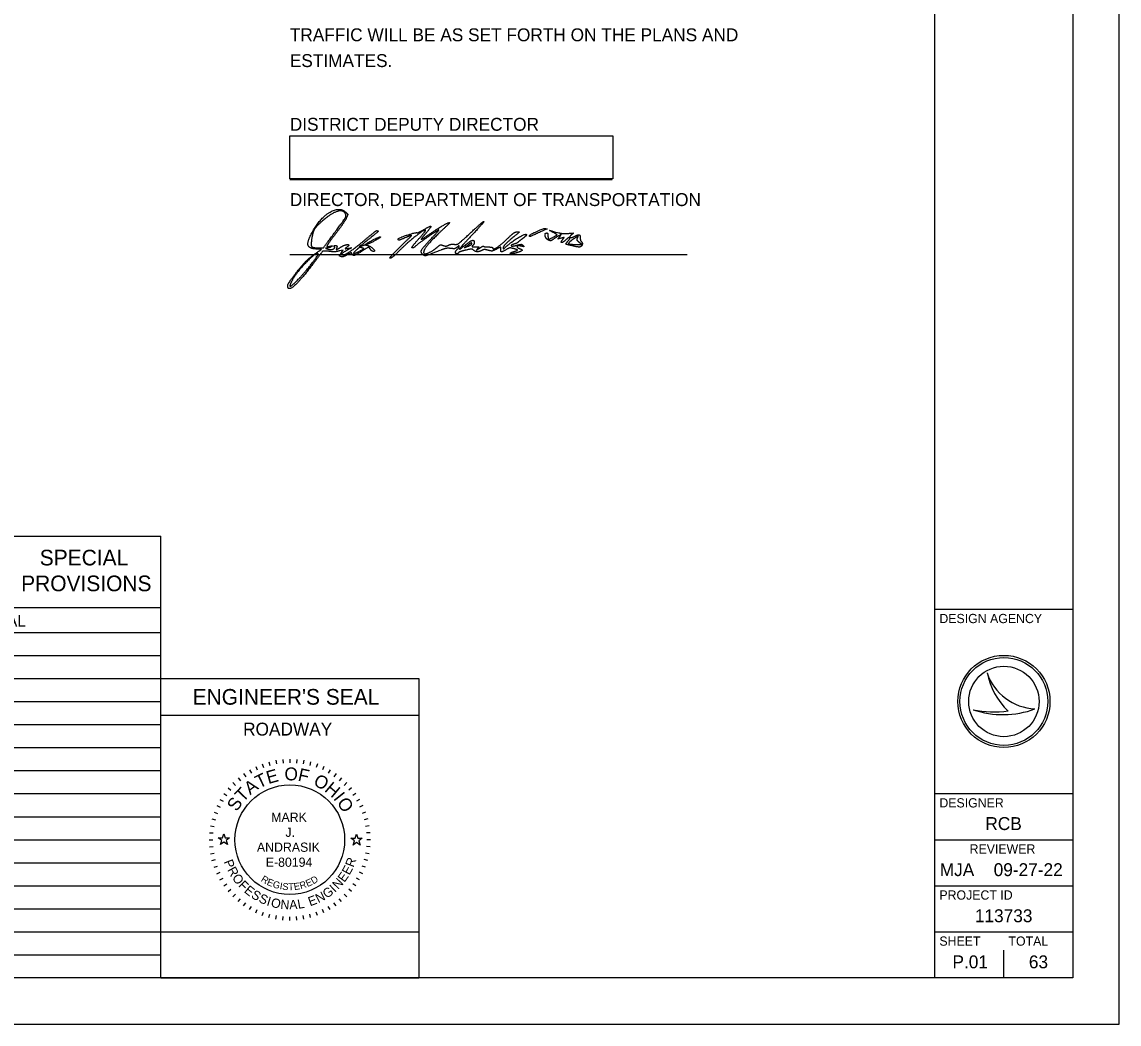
# Model space of a CAD drawing. Extents: x 0 to 34, y 0 to 22.
# Drawn here: x 22.09 to 34, y 0 to 10.87 of the extents above; entities that cross this region are included whole.
import ezdxf

# ---------------------------------------------------------------- set-up
doc = ezdxf.new("R2010")
doc.units = 0
for name, color, linetype in [('SH_Border', 7, 'Continuous'), ('SH_Cut_Line', 7, 'Continuous'), ('SH_Data', 7, 'Continuous'), ('SH_Text', 7, 'Continuous')]:
    doc.layers.add(name, color=color, linetype=linetype)

msp = doc.modelspace()

# ---------------------------------------------------------------- linework, layer by layer
at = {"layer": 'SH_Border'}
for p, q in [((32, 0.5), (32, 21.5)), ((32, 4.5), (33.5, 4.5)), ((32, 2.5), (33.5, 2.5)), ((32, 2), (33.5, 2)), ((32, 1.5), (33.5, 1.5)), ((32, 1), (33.5, 1))]:
    msp.add_line(p, q, dxfattribs=at)
msp.add_lwpolyline([(1.5, 21.5), (33.5, 21.5), (33.5, 0.5), (1.5, 0.5)], close=True, dxfattribs=at)
at = {"layer": 'SH_Cut_Line'}
msp.add_lwpolyline([(0, 0), (34, 0), (34, 22), (0, 22)], close=True, dxfattribs=at)
at = {"layer": 'SH_Data'}
for p, q in [((25, 9.162), (28.5, 9.162)), ((25, 8.348), (29.314, 8.348)), ((10.15, 5.292), (23.6, 5.292)), ((23.6, 0.5), (23.6, 5.292)), ((10.15, 4.521), (23.6, 4.521)), ((10.15, 4.25), (23.6, 4.25)), ((10.15, 4), (23.6, 4)), ((10.15, 3.75), (23.6, 3.75)), ((23.6, 0.5), (23.6, 3.75)), ((23.6, 3.75), (26.4, 3.75)), ((26.4, 3.75), (26.4, 0.5)), ((32.567, 3.81), (32.567, 3.81)), ((10.15, 3.5), (23.6, 3.5)), ((32.75, 3.5), (32.75, 3.5)), ((23.6, 3.35), (26.4, 3.35)), ((32.417, 3.41), (32.417, 3.41)), ((33.087, 3.419), (33.087, 3.419)), ((10.15, 3.25), (23.6, 3.25)), ((10.15, 3), (23.6, 3)), ((24.848, 2.862), (24.855, 2.822)), ((24.924, 2.872), (24.927, 2.832)), ((25, 2.875), (25, 2.835)), ((25.076, 2.872), (25.073, 2.832)), ((25.152, 2.862), (25.145, 2.822)), ((10.15, 2.75), (23.6, 2.75)), ((24.563, 2.758), (24.583, 2.723)), ((24.63, 2.793), (24.647, 2.757)), ((24.701, 2.822), (24.714, 2.785)), ((24.774, 2.845), (24.784, 2.807)), ((25.226, 2.845), (25.216, 2.807)), ((25.299, 2.822), (25.286, 2.785)), ((25.37, 2.793), (25.353, 2.757)), ((25.437, 2.758), (25.417, 2.723)), ((24.438, 2.67), (24.463, 2.64)), ((24.498, 2.717), (24.521, 2.684)), ((25.502, 2.717), (25.479, 2.684)), ((25.562, 2.67), (25.537, 2.64)), ((24.283, 2.502), (24.316, 2.479)), ((24.33, 2.562), (24.36, 2.537)), ((24.381, 2.619), (24.41, 2.59)), ((25.619, 2.619), (25.59, 2.59)), ((25.67, 2.562), (25.64, 2.537)), ((25.717, 2.502), (25.684, 2.479)), ((10.15, 2.5), (23.6, 2.5)), ((24.242, 2.438), (24.277, 2.418)), ((25.758, 2.438), (25.723, 2.418)), ((24.178, 2.299), (24.215, 2.286)), ((24.207, 2.37), (24.243, 2.353)), ((25.793, 2.37), (25.757, 2.353)), ((25.822, 2.299), (25.785, 2.286)), ((10.15, 2.25), (23.6, 2.25)), ((24.138, 2.152), (24.178, 2.145)), ((24.155, 2.226), (24.193, 2.216)), ((25.845, 2.226), (25.807, 2.216)), ((25.862, 2.152), (25.822, 2.145)), ((24.128, 2.076), (24.168, 2.073)), ((25.872, 2.076), (25.832, 2.073)), ((10.15, 2), (23.6, 2)), ((24.125, 2), (24.165, 2)), ((24.128, 1.924), (24.168, 1.927)), ((25.872, 1.924), (25.832, 1.927)), ((25.875, 2), (25.835, 2)), ((24.138, 1.848), (24.178, 1.855)), ((25.862, 1.848), (25.822, 1.855)), ((10.15, 1.75), (23.6, 1.75)), ((24.155, 1.774), (24.193, 1.784)), ((24.178, 1.701), (24.215, 1.714)), ((25.822, 1.701), (25.785, 1.714)), ((25.845, 1.774), (25.807, 1.784)), ((24.207, 1.63), (24.243, 1.647)), ((24.242, 1.563), (24.277, 1.583)), ((25.758, 1.563), (25.723, 1.583)), ((25.793, 1.63), (25.757, 1.647)), ((10.15, 1.5), (23.6, 1.5)), ((24.283, 1.498), (24.316, 1.521)), ((24.33, 1.438), (24.36, 1.463)), ((25.67, 1.438), (25.64, 1.463)), ((25.717, 1.498), (25.684, 1.521)), ((24.381, 1.381), (24.41, 1.41)), ((24.438, 1.33), (24.463, 1.36)), ((24.498, 1.283), (24.521, 1.316)), ((25.502, 1.283), (25.479, 1.316)), ((25.562, 1.33), (25.537, 1.36)), ((25.619, 1.381), (25.59, 1.41)), ((10.15, 1.25), (23.6, 1.25)), ((24.563, 1.242), (24.583, 1.277)), ((24.63, 1.207), (24.647, 1.243)), ((24.701, 1.178), (24.714, 1.215)), ((24.774, 1.155), (24.784, 1.193)), ((25.226, 1.155), (25.216, 1.193)), ((25.299, 1.178), (25.286, 1.215)), ((25.37, 1.207), (25.353, 1.243)), ((25.437, 1.242), (25.417, 1.277)), ((24.848, 1.138), (24.855, 1.178)), ((24.924, 1.128), (24.927, 1.168)), ((25, 1.125), (25, 1.165)), ((25.076, 1.128), (25.073, 1.168)), ((25.152, 1.138), (25.145, 1.178)), ((10.15, 1), (23.6, 1)), ((10.15, 0.75), (23.6, 0.75)), ((32.75, 0.5), (32.75, 0.8)), ((32.375, 0.675), (32.375, 0.675)), ((23.6, 0.5), (26.4, 0.5))]:
    msp.add_line(p, q, dxfattribs=at)
for points in [[(25, 9.172), (25, 9.637), (28.504, 9.637), (28.504, 9.172)], [(24.224, 2.02), (24.271, 2.02), (24.285, 2.065), (24.299, 2.02), (24.346, 2.02), (24.308, 1.992), (24.323, 1.948), (24.285, 1.975), (24.247, 1.948), (24.262, 1.992)], [(25.663, 2.015), (25.71, 2.015), (25.724, 2.059), (25.739, 2.015), (25.785, 2.015), (25.748, 1.987), (25.762, 1.942), (25.724, 1.97), (25.686, 1.942), (25.701, 1.987)], [(23.6, 0.5), (23.6, 1), (26.4, 1), (26.4, 0.5)]]:
    msp.add_lwpolyline(points, close=True, dxfattribs=at)
for centre, radius in [((32.75, 3.5), 0.5), ((32.75, 3.5), 0.477), ((32.75, 3.5), 0.477), ((32.75, 3.5), 0.382), ((25, 2), 0.595)]:
    msp.add_circle(centre, radius, dxfattribs=at)
for centre, radius, start, end in [((33.116, 3.998), 0.58, 198.9257, 198.9319), ((33.347, 3.97), 0.796, 191.6379, 191.6421), ((33.116, 3.998), 0.58, 198.9319, 267.1657), ((33.347, 3.97), 0.796, 191.6421, 226.0947), ((32.739, 4.37), 1.013, 251.4576, 290.0832), ((32.648, 4.654), 1.266, 259.4964, 259.4995), ((32.739, 4.37), 1.013, 251.4527, 251.4576), ((32.648, 4.654), 1.266, 259.4995, 276.6672)]:
    msp.add_arc(centre, radius, start, end, dxfattribs=at)
at = {"layer": 'SH_Text'}
for p, q in [((25.462, 8.553), (25.462, 8.553)), ((25.828, 8.463), (25.828, 8.463)), ((26.977, 8.465), (26.977, 8.465)), ((27.602, 8.552), (27.602, 8.552)), ((25.783, 8.421), (25.783, 8.421)), ((26.199, 8.434), (26.199, 8.434)), ((28.054, 8.446), (28.054, 8.446)), ((24.977, 8.013), (24.977, 8.013)), ((25.092, 8.08), (25.092, 8.08))]:
    msp.add_line(p, q, dxfattribs=at)
for points in [[(27.865, 8.542), (27.902, 8.564), (27.861, 8.587)], [(28.114, 8.459), (28.17, 8.459), (28.142, 8.481)], [(25.315, 8.386), (25.345, 8.407), (25.307, 8.408)], [(25.558, 8.366), (25.579, 8.398), (25.537, 8.388)], [(26.925, 8.445), (26.895, 8.42), (26.936, 8.439)]]:
    msp.add_lwpolyline(points, dxfattribs=at)
for points in [[(25.251, 8.604), (25.337, 8.754), (25.545, 8.87), (25.611, 8.804)], [(25.602, 8.795), (25.576, 8.837), (25.45, 8.796), (25.355, 8.714)], [(25.355, 8.714), (25.288, 8.657), (25.249, 8.593), (25.238, 8.522)], [(25.462, 8.553), (25.584, 8.716), (25.616, 8.772), (25.602, 8.795)], [(25.612, 8.742), (25.601, 8.719), (25.549, 8.643), (25.497, 8.574)], [(25.611, 8.804), (25.63, 8.785), (25.63, 8.78), (25.612, 8.742)], [(26.505, 8.562), (26.585, 8.619), (26.717, 8.696), (26.732, 8.696)], [(26.732, 8.696), (26.737, 8.696), (26.696, 8.653), (26.64, 8.601)], [(26.959, 8.582), (27.034, 8.651), (27.1, 8.708), (27.106, 8.708)], [(27.106, 8.708), (27.111, 8.708), (27.059, 8.648), (26.99, 8.574)], [(25.307, 8.408), (25.21, 8.409), (25.186, 8.49), (25.251, 8.604)], [(25.497, 8.574), (25.444, 8.505), (25.402, 8.444), (25.402, 8.439)], [(25.841, 8.53), (25.892, 8.573), (25.937, 8.608), (25.942, 8.608)], [(25.942, 8.608), (25.967, 8.609), (25.944, 8.583), (25.858, 8.516)], [(26.474, 8.615), (26.464, 8.625), (26.254, 8.458), (26.177, 8.379)], [(26.177, 8.518), (26.177, 8.528), (26.364, 8.591), (26.38, 8.586)], [(26.614, 8.615), (26.565, 8.587), (26.377, 8.455), (26.363, 8.439)], [(26.38, 8.586), (26.386, 8.584), (26.415, 8.598), (26.446, 8.615)], [(26.396, 8.515), (26.442, 8.567), (26.477, 8.612), (26.474, 8.615)], [(26.478, 8.581), (26.45, 8.549), (26.427, 8.52), (26.427, 8.515)], [(26.446, 8.615), (26.525, 8.662), (26.537, 8.648), (26.478, 8.581)], [(26.64, 8.601), (26.541, 8.507), (26.452, 8.399), (26.452, 8.372)], [(26.549, 8.536), (26.595, 8.585), (26.624, 8.621), (26.614, 8.615)], [(26.784, 8.46), (26.817, 8.457), (26.841, 8.474), (26.959, 8.582)], [(26.99, 8.574), (26.861, 8.437), (26.829, 8.39), (26.911, 8.457)], [(27.367, 8.526), (27.412, 8.57), (27.45, 8.596), (27.467, 8.595)], [(27.467, 8.595), (27.492, 8.595), (27.488, 8.588), (27.439, 8.548)], [(27.602, 8.552), (27.602, 8.564), (27.754, 8.635), (27.773, 8.631)], [(27.773, 8.631), (27.794, 8.627), (27.795, 8.627), (27.673, 8.573)], [(27.803, 8.508), (27.776, 8.522), (27.765, 8.583), (27.789, 8.583)], [(27.789, 8.583), (27.796, 8.583), (27.802, 8.569), (27.802, 8.552)], [(27.861, 8.587), (27.818, 8.611), (27.817, 8.611), (27.92, 8.585)], [(27.92, 8.585), (27.941, 8.579), (27.986, 8.576), (28.02, 8.578)], [(28.02, 8.578), (28.075, 8.582), (28.08, 8.58), (28.06, 8.565)], [(25.238, 8.522), (25.227, 8.449), (25.248, 8.421), (25.316, 8.421)], [(25.316, 8.421), (25.363, 8.421), (25.367, 8.425), (25.462, 8.553)], [(25.546, 8.425), (25.575, 8.445), (25.639, 8.463), (25.639, 8.451)], [(25.58, 8.346), (25.603, 8.346), (25.729, 8.435), (25.841, 8.53)], [(25.858, 8.516), (25.765, 8.443), (25.743, 8.421), (25.787, 8.445)], [(25.831, 8.458), (25.826, 8.458), (25.825, 8.46), (25.828, 8.463)], [(25.828, 8.463), (25.848, 8.481), (25.98, 8.547), (25.985, 8.541)], [(25.985, 8.541), (25.991, 8.535), (25.849, 8.458), (25.831, 8.458)], [(26.258, 8.533), (26.195, 8.506), (26.176, 8.503), (26.177, 8.518)], [(26.199, 8.434), (26.27, 8.502), (26.326, 8.558), (26.322, 8.558)], [(26.322, 8.558), (26.319, 8.558), (26.29, 8.547), (26.258, 8.533)], [(26.33, 8.421), (26.32, 8.421), (26.349, 8.462), (26.396, 8.515)], [(26.442, 8.35), (26.417, 8.375), (26.446, 8.426), (26.549, 8.536)], [(26.427, 8.515), (26.427, 8.511), (26.462, 8.532), (26.505, 8.562)], [(26.609, 8.436), (26.629, 8.454), (26.642, 8.456), (26.666, 8.447)], [(26.721, 8.45), (26.734, 8.457), (26.763, 8.462), (26.784, 8.46)], [(26.911, 8.457), (26.959, 8.497), (27.002, 8.508), (27.002, 8.48)], [(26.977, 8.465), (26.977, 8.478), (26.952, 8.469), (26.925, 8.445)], [(26.936, 8.439), (26.958, 8.45), (26.977, 8.462), (26.977, 8.465)], [(27.002, 8.48), (27.002, 8.471), (26.995, 8.457), (26.987, 8.448)], [(27.202, 8.419), (27.202, 8.396), (27.297, 8.458), (27.367, 8.526)], [(27.439, 8.548), (27.365, 8.487), (27.314, 8.434), (27.314, 8.417)], [(27.348, 8.435), (27.402, 8.484), (27.549, 8.574), (27.566, 8.568)], [(27.442, 8.465), (27.393, 8.45), (27.412, 8.436), (27.464, 8.45)], [(27.477, 8.482), (27.473, 8.478), (27.458, 8.47), (27.442, 8.465)], [(27.464, 8.45), (27.502, 8.46), (27.518, 8.46), (27.53, 8.448)], [(27.532, 8.526), (27.505, 8.506), (27.48, 8.486), (27.477, 8.482)], [(27.566, 8.568), (27.574, 8.565), (27.559, 8.547), (27.532, 8.526)], [(27.673, 8.573), (27.611, 8.545), (27.602, 8.542), (27.602, 8.552)], [(27.802, 8.552), (27.802, 8.515), (27.816, 8.513), (27.865, 8.542)], [(27.877, 8.526), (27.837, 8.5), (27.824, 8.496), (27.803, 8.508)], [(27.925, 8.537), (27.949, 8.567), (27.934, 8.563), (27.877, 8.526)], [(27.944, 8.526), (27.911, 8.518), (27.909, 8.519), (27.925, 8.537)], [(27.964, 8.515), (27.979, 8.533), (27.977, 8.534), (27.944, 8.526)], [(27.993, 8.506), (27.961, 8.476), (27.938, 8.483), (27.964, 8.515)], [(28.018, 8.494), (28.049, 8.527), (28.027, 8.538), (27.993, 8.506)], [(28.054, 8.446), (27.999, 8.459), (27.994, 8.466), (28.018, 8.494)], [(28.061, 8.504), (28.018, 8.473), (28.035, 8.459), (28.114, 8.459)], [(28.06, 8.565), (28.031, 8.544), (28.054, 8.527), (28.088, 8.545)], [(28.122, 8.527), (28.132, 8.552), (28.124, 8.549), (28.061, 8.504)], [(28.088, 8.545), (28.128, 8.567), (28.152, 8.561), (28.152, 8.53)], [(28.142, 8.481), (28.121, 8.497), (28.115, 8.51), (28.122, 8.527)], [(28.152, 8.53), (28.152, 8.514), (28.158, 8.494), (28.166, 8.487)], [(28.166, 8.487), (28.174, 8.479), (28.177, 8.464), (28.172, 8.453)], [(25.308, 8.357), (25.287, 8.377), (25.068, 8.152), (25.022, 8.061)], [(25.064, 8.144), (25.141, 8.244), (25.221, 8.321), (25.315, 8.386)], [(25.092, 8.08), (25.159, 8.149), (25.315, 8.349), (25.308, 8.357)], [(25.396, 8.386), (25.362, 8.389), (25.351, 8.379), (25.274, 8.277)], [(25.408, 8.42), (25.385, 8.419), (25.386, 8.418), (25.412, 8.408)], [(25.537, 8.388), (25.497, 8.378), (25.474, 8.378), (25.396, 8.386)], [(25.402, 8.439), (25.402, 8.435), (25.417, 8.434), (25.436, 8.439)], [(25.452, 8.434), (25.441, 8.427), (25.422, 8.421), (25.408, 8.42)], [(25.412, 8.408), (25.442, 8.396), (25.498, 8.42), (25.481, 8.438)], [(25.436, 8.439), (25.461, 8.445), (25.465, 8.443), (25.452, 8.434)], [(25.481, 8.438), (25.476, 8.442), (25.482, 8.446), (25.495, 8.446)], [(25.495, 8.446), (25.509, 8.446), (25.514, 8.439), (25.51, 8.427)], [(25.51, 8.427), (25.501, 8.404), (25.513, 8.403), (25.546, 8.425)], [(25.556, 8.326), (25.538, 8.333), (25.538, 8.337), (25.558, 8.366)], [(25.623, 8.346), (25.597, 8.331), (25.567, 8.322), (25.556, 8.326)], [(25.624, 8.397), (25.573, 8.368), (25.553, 8.346), (25.58, 8.346)], [(25.617, 8.427), (25.599, 8.413), (25.601, 8.411), (25.633, 8.416)], [(25.639, 8.451), (25.639, 8.446), (25.629, 8.435), (25.617, 8.427)], [(25.674, 8.36), (25.671, 8.368), (25.652, 8.363), (25.623, 8.346)], [(25.633, 8.416), (25.67, 8.422), (25.67, 8.422), (25.624, 8.397)], [(25.789, 8.389), (25.72, 8.345), (25.682, 8.335), (25.674, 8.36)], [(25.73, 8.405), (25.685, 8.364), (25.697, 8.355), (25.755, 8.385)], [(25.783, 8.421), (25.766, 8.428), (25.749, 8.422), (25.73, 8.405)], [(25.755, 8.385), (25.801, 8.409), (25.805, 8.413), (25.783, 8.421)], [(25.787, 8.445), (25.8, 8.452), (25.824, 8.454), (25.84, 8.449)], [(25.873, 8.408), (25.856, 8.432), (25.854, 8.432), (25.789, 8.389)], [(25.84, 8.449), (25.876, 8.44), (25.935, 8.383), (25.908, 8.383)], [(25.908, 8.383), (25.898, 8.383), (25.883, 8.394), (25.873, 8.408)], [(26.089, 8.309), (26.079, 8.309), (26.128, 8.365), (26.199, 8.434)], [(26.177, 8.379), (26.139, 8.34), (26.099, 8.309), (26.089, 8.309)], [(26.363, 8.439), (26.355, 8.429), (26.34, 8.421), (26.33, 8.421)], [(26.641, 8.398), (26.495, 8.34), (26.46, 8.332), (26.442, 8.35)], [(26.452, 8.372), (26.452, 8.365), (26.46, 8.358), (26.47, 8.358)], [(26.47, 8.358), (26.491, 8.358), (26.573, 8.404), (26.609, 8.436)], [(26.747, 8.415), (26.718, 8.419), (26.678, 8.412), (26.641, 8.398)], [(26.666, 8.447), (26.686, 8.44), (26.705, 8.441), (26.721, 8.45)], [(26.817, 8.429), (26.801, 8.415), (26.78, 8.411), (26.747, 8.415)], [(26.813, 8.358), (26.795, 8.358), (26.8, 8.391), (26.82, 8.408)], [(26.832, 8.369), (26.828, 8.363), (26.82, 8.358), (26.813, 8.358)], [(26.839, 8.437), (26.839, 8.444), (26.829, 8.441), (26.817, 8.429)], [(26.82, 8.408), (26.831, 8.417), (26.839, 8.43), (26.839, 8.437)], [(26.908, 8.396), (26.869, 8.387), (26.835, 8.374), (26.832, 8.369)], [(26.992, 8.398), (26.981, 8.409), (26.961, 8.409), (26.908, 8.396)], [(26.987, 8.448), (26.975, 8.437), (26.981, 8.433), (27.013, 8.433)], [(27.088, 8.395), (27.058, 8.379), (27.01, 8.38), (26.992, 8.398)], [(27.013, 8.433), (27.051, 8.433), (27.053, 8.431), (27.037, 8.412)], [(27.037, 8.412), (27.025, 8.397), (27.032, 8.399), (27.059, 8.418)], [(27.059, 8.418), (27.081, 8.433), (27.101, 8.442), (27.105, 8.438)], [(27.153, 8.395), (27.126, 8.403), (27.103, 8.403), (27.088, 8.395)], [(27.105, 8.438), (27.109, 8.434), (27.132, 8.431), (27.157, 8.431)], [(27.242, 8.407), (27.204, 8.388), (27.186, 8.386), (27.153, 8.395)], [(27.157, 8.431), (27.182, 8.431), (27.202, 8.426), (27.202, 8.419)], [(27.289, 8.407), (27.289, 8.43), (27.288, 8.43), (27.242, 8.407)], [(27.351, 8.404), (27.306, 8.377), (27.289, 8.378), (27.289, 8.407)], [(27.314, 8.417), (27.314, 8.41), (27.33, 8.418), (27.348, 8.435)], [(27.434, 8.412), (27.395, 8.422), (27.379, 8.42), (27.351, 8.404)], [(27.47, 8.371), (27.424, 8.355), (27.376, 8.361), (27.42, 8.377)], [(27.42, 8.377), (27.434, 8.382), (27.454, 8.389), (27.464, 8.393)], [(27.464, 8.393), (27.475, 8.397), (27.464, 8.404), (27.434, 8.412)], [(27.511, 8.44), (27.474, 8.449), (27.461, 8.426), (27.495, 8.413)], [(27.495, 8.413), (27.526, 8.401), (27.517, 8.386), (27.47, 8.371)], [(27.53, 8.448), (27.542, 8.435), (27.539, 8.433), (27.511, 8.44)], [(28.172, 8.453), (28.164, 8.432), (28.123, 8.429), (28.054, 8.446)], [(25.274, 8.277), (25.122, 8.075), (24.977, 7.946), (24.977, 8.013)], [(24.977, 8.013), (24.977, 8.023), (25.016, 8.082), (25.064, 8.144)], [(25.022, 8.061), (24.991, 8), (25.022, 8.009), (25.092, 8.08)]]:
    msp.add_open_spline(points, degree=2, dxfattribs=at)

# ---------------------------------------------------------------- texts
at = {"layer": 'SH_Data'}
for s, height, p in [('TRAFFIC WILL BE AS SET FORTH ON THE PLANS AND', 0.14, (25, 10.663)), ('ESTIMATES.', 0.14, (25, 10.383)), ('DESIGN AGENCY', 0.1, (32.05, 4.35)), ("ENGINEER'S SEAL", 0.17, (23.945, 3.465)), ('ROADWAY', 0.14, (24.493, 3.13)), ('DESIGNER', 0.1, (32.05, 2.35)), ('MARK', 0.1, (24.798, 2.194)), ('RCB', 0.14, (32.549, 2.105)), ('J.', 0.1, (24.952, 2.031)), ('ANDRASIK', 0.1, (24.643, 1.869)), ('REVIEWER', 0.1, (32.378, 1.85)), ('E-80194', 0.1, (24.739, 1.706)), ('MJA', 0.14, (32.054, 1.605)), ('09-27-22', 0.14, (32.639, 1.605)), ('PROJECT ID', 0.1, (32.05, 1.35)), ('113733', 0.14, (32.435, 1.105)), ('SHEET', 0.1, (32.05, 0.85)), ('TOTAL', 0.1, (32.8, 0.85)), ('P.01', 0.14, (32.192, 0.605)), ('63', 0.14, (33.021, 0.605))]:
    msp.add_text(s, height=height, dxfattribs=at).set_placement(p)
for s, height, rotation, p in [('E', 0.14, 15.7571, (24.767, 2.603)), ('O', 0.14, 359.7812, (24.942, 2.644)), ('F', 0.14, 347.4362, (25.081, 2.642)), ('A', 0.14, 36.4747, (24.569, 2.482)), ('T', 0.14, 25.7167, (24.666, 2.554)), ('O', 0.14, 332.2586, (25.246, 2.598)), ('H', 0.14, 319.9136, (25.368, 2.532)), ('T', 0.14, 46.4344, (24.492, 2.4)), ('I', 0.14, 308.367, (25.467, 2.447)), ('S', 0.14, 57.1924, (24.426, 2.298)), ('O', 0.14, 303.1491, (25.506, 2.403)), ('P', 0.1, 291.494, (24.282, 1.762)), ('R', 0.1, 69.2322, (25.691, 1.694)), ('R', 0.1, 298.7311, (24.318, 1.673)), ('E', 0.1, 61.9951, (25.647, 1.609)), ('O', 0.1, 306.4666, (24.368, 1.585)), ('F', 0.1, 314.7068, (24.434, 1.498)), ('R', 0.075, 327.8239, (24.68, 1.554)), ('E', 0.075, 337.7777, (24.744, 1.513)), ('G', 0.075, 344.2727, (24.808, 1.485)), ('R', 0.075, 17.6836, (25.119, 1.463)), ('E', 0.075, 23.3052, (25.191, 1.486)), ('D', 0.075, 31.466, (25.255, 1.514)), ('N', 0.1, 47.0224, (25.524, 1.455)), ('E', 0.1, 54.758, (25.593, 1.531)), ('E', 0.1, 321.4393, (24.497, 1.435)), ('S', 0.1, 328.6764, (24.572, 1.377)), ('I', 0.075, 350.6464, (24.887, 1.463)), ('S', 0.075, 353.7858, (24.915, 1.458)), ('T', 0.075, 3.0061, (24.985, 1.451)), ('E', 0.075, 8.9826, (25.049, 1.453)), ('N', 0.1, 27.3113, (25.31, 1.31)), ('G', 0.1, 35.0469, (25.4, 1.358)), ('I', 0.1, 43.287, (25.488, 1.422)), ('S', 0.1, 335.9134, (24.654, 1.328)), ('I', 0.1, 343.1505, (24.742, 1.289)), ('O', 0.1, 346.8859, (24.788, 1.274)), ('N', 0.1, 355.1261, (24.895, 1.251)), ('A', 0.1, 2.8617, (24.996, 1.244)), ('L', 0.1, 10.0987, (25.092, 1.249)), ('E', 0.1, 20.0742, (25.22, 1.277))]:
    msp.add_text(s, height=height, rotation=rotation, dxfattribs=at).set_placement(p)
at = {"layer": 'SH_Text'}
for s, height, p in [('DISTRICT DEPUTY DIRECTOR', 0.14, (25, 9.692)), ('DIRECTOR, DEPARTMENT OF TRANSPORTATION', 0.14, (25, 8.875)), ('SPECIAL', 0.17, (22.286, 4.976)), ('PROVISIONS', 0.17, (22.084, 4.696)), ('SEE PROPOSAL', 0.125, (20.835, 4.312))]:
    msp.add_text(s, height=height, dxfattribs=at).set_placement(p)

doc.saveas('drawing.dxf')
